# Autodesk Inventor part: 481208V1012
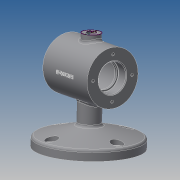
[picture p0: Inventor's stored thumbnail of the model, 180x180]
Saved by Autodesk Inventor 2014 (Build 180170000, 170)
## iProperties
Created: 2018-12
Part Number: 481208V1012
Material: 일반
Document SubType Name: Modeling
Designer: 601-24
Density: 1 g/cm^3
Appearance: 기본값
Author: 601-24
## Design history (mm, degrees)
sketch "스케치1"
  geometry: L1 (-35, 75)-(35, 75); L2 (-35, 92)-(-35, 105); L3 (-35, 105)-(35, 105); L4 (35, 105)-(35, 92); L5 (34, 91)-(23.3, 91); L6 (23, 90.7)-(23, 89); L7 (23, 89)-(20, 89); L8 (20, 89)-(20, 97); L9 (17, 100)-(-17, 100); L10 (-20, 97)-(-20, 89); L11 (-20, 89)-(-23, 89); L12 (-23, 89)-(-23, 90.7); L13 (-23.3, 91)-(-34, 91); L14 (-34, 91)-(-35, 92); L15 (34, 91)-(35, 92); A1 r 3 centre (17, 97) between (20, 97) and (17, 100); A2 r 3 centre (-17, 97) between (-17, 100) and (-20, 97); A3 r 0.3 centre (-23.3, 90.7) between (-23, 90.7) and (-23.3, 91); A4 r 0.3 centre (23.3, 90.7) between (23.3, 91) and (23, 90.7); 10 further points
  constraints: 30 end point, 20 point on line, 8 point on circle, 8 tangent, 7 perpendicular, 4 centre point, 4 parallel, 2 equal radius, 1 horizontal, 1 midpoint, 1 vertical alignment
  dimensions: "d0" = 70 distance of L1.start L1.end; "d1" = 75 distance from line of L1 point (0, 0); "d2" = 30 distance of L1.start L2.end; "d3" = 12 distance of point (35, 91) point (23, 91); "d4" = 40 distance of point (20, 100) point (-20, 100); "d5" = 12 distance of point (-23, 91) point (-35, 91); "d6" = 3 distance of L10.end L11.end; "d7" = 50 diameter of L9 L1; "d8" = 28 diameter of L11 L1; "d9" = 32 diameter of L13 L1; "d10" = 28 diameter of L7 L1; "d11" = 3 radius of A1; "d12" = 0.3 radius of A3; "d13" = 1 distance of L13.end point (-35, 91); "d14" = 1 distance of L2.start point (-35, 91) (= d13); "d15" = 1 distance of L5.start point (35, 91) (= d13); "d16" = 1 distance of L4.end point (35, 91) (= d15)
revolve "회전1" sketch "스케치1" stored, may be unused: angle "d17" = 90 deg
sketch "스케치2"
  geometry: C1 r 55 at (0, 0); C2 r 12 at (0, 0); C3 r 7 at (0, 44); C4 r 4.5 at (0, 44); C5 r 7 at (-44, 0); C6 r 4.5 at (-44, 0); C7 r 7 at (44, 0); C8 r 4.5 at (44, 0); C9 r 7 at (0, -44); C10 r 4.5 at (0, -44); A1 r 44 centre (0, 0) between (0, 44) and (-44, 0); 1 further point
  constraints: 11 centre point, 6 coincident, 5 point on circle
  dimensions: "d18" = 110 diameter of C1; "d19" = 24 diameter of C2; "d20" = 88 diameter of A1; "d21" = 14 diameter of C3; "d22" = 9 diameter of C4; "d23" = 14 diameter of C5; "d24" = 9 diameter of C6; "d25" = 14 diameter of C7; "d26" = 9 diameter of C8; "d27" = 14 diameter of C9; "d28" = 9 diameter of C10
sketch "스케치3"
  geometry: L1 (55, 10)-(-55, 10) reference; L2 (-35, 45)-(35, 45) reference; 1 further point
extrude "돌출3" join sketch "스케치2" stored distance "d33" = 10; taper "d34" = 0 deg
sketch "스케치5"
  geometry: L1 (0, 0)-(55, 0); L2 (55, 0)-(55, 8.698); L3 (52.776, 11.596)-(12, 22.522); L4 (12, 0)-(12, 45) reference; L5 (12, 22.522)-(12, 0); L6 (0, 0)-(0, 6.822); L7 (12, 0)-(55, 0); A1 r 3 centre (52, 8.698) between (55, 8.698) and (52.776, 11.596); 1 further point
  constraints: 12 end point, 3 point on line, 2 collinear, 2 point on circle, 2 tangent, 1 centre point, 1 horizontal, 1 parallel, 1 perpendicular
  dimensions: "d40" = 55 distance of L1.start L1.end; "d41" = 11 distance of L1.end point (55, 11); "d43" = 105 deg angle of L2 L3; "d44" = 3 radius of A1
revolve "회전3" sketch "스케치5" stored, may be unused: angle "d45" = 90 deg
fillet "모깎기1" dims "d46" = 3
fillet "모깎기2" dims "d47" = 3
sketch "스케치6" dims "d48" = 46
  geometry: C1 r 30 at (0, 0) reference; 3 further points
  constraints: 1 coincident, 1 vertical alignment, 2 other
hole "구멍1" sketch "스케치6" at (0, 23) diameter "d49" = 3.242; stored, may be unused: countersink angle "d53" = 90 deg, drill point angle "d55" = 118 deg; dims "d50" = 8, "d51" = 4, "d52" = 2, "d54" = 10
node "작업 평면1"
sketch "스케치7"
  geometry: C1 r 7 at (0, 44) reference; C2 r 7 at (44, 0) reference; C3 r 7 at (0, -44) reference; C4 r 7 at (-44, 0) reference; C5 r 7 at (0, 44); C6 r 7 at (-44, 0); C7 r 7 at (44, 0); C8 r 7 at (0, -44); 1 further point
  constraints: 4 centre point, 4 coincident, 4 concentric
extrude "돌출5" cut sketch "스케치7" distance "d60" = 20; taper "d61" = 0 deg
extrude "돌출6" cut sketch "스케치2" distance "d62" = 20; taper "d63" = 0 deg
node "작업 평면2"
sketch "스케치8"
  geometry: C1 r 10 at (0, 0); C2 r 5 at (0, 0); 1 further point
  constraints: 2 centre point, 2 coincident
  dimensions: "d65" = 20 diameter of C1; "d66" = 10 diameter of C2
extrude "돌출7" join sketch "스케치8" stored distance "d67" = 20; taper "d68" = 0 deg
extrude "돌출8" cut sketch "스케치8" stored distance "d69" = 20; taper "d70" = 0 deg
fillet "모깎기3" dims "d71" = 3
chamfer "모따기1" distance "d72" = 1; stored, may be unused: second distance "d73" = 2, angle "d74" = 45 deg
node "작업 평면3"
sketch "스케치9"
  geometry: L1 (-35, 105)-(35, 105) reference; L2 (-35, 45)-(-35, 105) reference; 2 further points
  constraints: 1 other
  dimensions: "d76" = 30 distance from line of L1 point (0, 75); "d77" = 35 distance from line of L2 point (0, 75)
feature "엠보싱1" sketch "스케치9" dims "d78" = 0.5, "d79" = 0
node "솔리드1"
pattern_circular "원형 패턴1" dims angle "d57" = 360 deg
mirror "대칭1"
other parameters: "d64" = 112
